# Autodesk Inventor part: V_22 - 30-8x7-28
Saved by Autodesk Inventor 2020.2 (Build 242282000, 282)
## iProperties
Manager: www.cadconsulting.pl
Company: Fabian Stasiak CAD Consulting
Created: 2006-02
Part Number: V_22 - 30-8x7-28
Material: Stal 60
Description: Wpust pryzmatyczny 8x7x28
Vendor: Autodesk Inc.
Document SubType Name: Modeling
Standard: DIN 6885
Designer: F.Stasiak
Standards Organization: DIN
Language: pl-PL
Size Designation: A 8 x 7 x 28
Categories: <MemberInstance Version="R10.0.0"><Categories><Category DisplayName="Części wałów" InternalName="7f7aeb1f-a693-4053-b835-cee3144e0d98" Mnemonic="SHFT"><Category
Stock Number: PFP 3R8728
Project: Przekładnia X51
Density: 7.85 g/cm^3
Appearance: Stal metaliczna (obrabiana_00)
Author: F.Stasiak
Subject: Zbiór ćwiczeń. Autodesk Inventor 2020. Kurs podstawowy
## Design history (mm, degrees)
node "IDS_WORKPLANE{1}"
node "IDS_WORKPLANE{2}"
sketch "Szkic1"
  geometry: L1 (4, 4)-(24, 4); L2 (24, -4)-(4, -4); L3 (0, 10.6)-(0, -6.2) reference; L4 (-2.5, 0)-(32.5, 0) reference; L5 (28, 0)-(28, 7); A1 r 4 centre (4, 0) between (4, 4) and (4, -4); A2 r 4 centre (24, 0) between (24, -4) and (24, 4)
  constraints: 6 end point, 5 point on circle, 4 tangent, 3 point on line, 2 centre point, 1 horizontal, 1 parallel, 1 perpendicular
  dimensions: "d0" = 4 radius of A1 (= 0.5 x PB); "d8" = 4 radius of A2 (= 0.5 x PB); "d9" = 28 distance between parallel lines of L5 L3 (= NLG)
extrude "Bryła1" new body sketch "Szkic1" taper "d3" = 0 deg; stored distance "d4" = 10
node "Bryła2"
node "Korpusy bryłowe"
node "Korpusy powierzchniowe"
other parameters: "d1" = -4 (= -PNT), "d2" = 3 (= PH - PNT), "NLG" = 28 [user parameter; used in 3 equation terms], "PB" = 8 [user parameter; used in 2 equation terms], "PNT" = 4 [user parameter; used in 2 equation terms], "d5" = 0, "d6" = 0, "PH" = 7 [user parameter; used in 1 equation term], "d7" = 0, "WDMIN" = 22 [user parameter], "PUEB" = 3.3 [user parameter], "PLB1" = 28 (= NLG) [user parameter], "PLB2" = 28 (= NLG) [user parameter], "PHH" = 0 [user parameter], "RR" = 0.001 [user parameter]
